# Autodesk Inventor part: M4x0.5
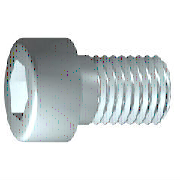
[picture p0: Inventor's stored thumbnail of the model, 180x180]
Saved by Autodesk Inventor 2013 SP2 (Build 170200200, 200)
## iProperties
IsCustomPart: 1
Company: 한국ATC센터
Created: 2014-11
Part Number: M4x0.5
Material: 강, 연강
Description: 6각머리 태핑 나사
Document SubType Name: Modeling
Standard: KS B 1003
Designer: KYOUNG IL JANG
Standards Organization: KS
Language: ko-KR
Size Designation: M 4 x 16
Categories: <MemberInstance><Categories><Category DisplayName="조임쇠" InternalName="e4da775c-781d-43d5-af7c-5136215cf5a6" Mnemonic="FSTN"><Category DisplayName="볼트" InternalN
Density: 7.86 g/cm^3
Mass: 2.62973 g
Surface Area: 3.81119 cm^2
Volume: 0.334572 cm^3
Author: KYOUNG IL JANG
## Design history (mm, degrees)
sketch "스케치1"
  geometry: L1 (-1, 0)-(16, 0); L2 (16, 0)-(16, 2); L3 (16, 2)-(1.75, 2); L4 (1.75, 2)-(1.32, 2); L5 (1.32, 2)-(0, 2); L6 (0, 2)-(0, 3.5); L7 (0, 3.5)-(-4, 3.5); L8 (-4, 3.5)-(-4, 1.732); L9 (-4, 1.732)-(-2, 1.732); L10 (-2, 1.732)-(-1, 0); L11 (-8, 0)-(20, 0) reference; L12 (0, -0.7)-(0, 4.2) reference; L13 (1.75, 2)-(0, 2)
  constraints: 22 end point, 6 parallel, 2 collinear, 2 perpendicular, 1 horizontal, 1 point on line
  dimensions: "d1" = 14.25 distance from line of L3.end L2 (= GEL); "d2" = 0.42952 distance of L4.end L3.end (computed from GAL); "d3" = 4 distance between parallel lines of L8 L6 (= KOH); "d4" = 2 distance of L8.end L9.end (= INTI); "d5" = 60 deg angle of L10 L1; "d6" = 4 diameter of L3 L1 (= GD); "d7" = 4 diameter of L5 L1 (= BDM); "d8" = 3.4641 diameter of L9 L1 (= 1.1547 x SW); "d9" = 7 diameter of L7 L1 (= KOD); "d26" = 16 distance between parallel lines of L12 L2 (= NLG)
revolve "본체" sketch "스케치1" stored, may be unused: angle "d10" = 90 deg
sketch "스케치2"
  geometry: L1 (0, -4.9)-(0, 4.9) reference; L2 (-4.9, 0)-(4.9, 0) reference; L3 (1.732, 0)-(0.866, -1.5); L4 (0.866, -1.5)-(-0.866, -1.5); L5 (-0.866, -1.5)-(-1.732, 0); L6 (-1.732, 0)-(-0.866, 1.5); L7 (-0.866, 1.5)-(0.866, 1.5); L8 (0.866, 1.5)-(1.732, 0); 2 further points
  constraints: 12 end point, 1 coincident, 1 horizontal alignment, 1 point on line, 12 other
extrude "슬롯" join sketch "스케치2" stored distance "d11" = 10; taper "d12" = 0 deg
workplane "Work Plane1"
fillet "Fillet2" dims "d30" = 0.1 (= R)
body "Solid1"
fillet "모깎기1" dims "d17" = 0.4 (= RR)
feature "스레드" dims "d13" = 14.25 (= GEL), "d14" = 0
chamfer "모따기1" distance "d15" = 0.42941 (= -0.5 x SPD + 0.5 x GD); stored, may be unused: second distance "d16" = 0.42941 (= GUL), angle "d27" = 45 deg
other parameters: "GD" = 4 (= NND) [user parameter; used in 2 equation terms], "NLG" = 16 [user parameter; used in 1 equation term], "GEL" = 14.25 [user parameter; used in 2 equation terms], "KOD" = 7 [user parameter; used in 1 equation term], "KOH" = 4 [user parameter; used in 1 equation term], "INTI" = 2 [user parameter; used in 1 equation term], "GAL" = 0.42941 (= 0.61345 x PTC) [user parameter; used in 1 equation term], "GUL" = 0.42941 (= 0.61345 x PTC) [user parameter; used in 1 equation term], "BDM" = 4 (= NND) [user parameter; used in 1 equation term], "SW" = 3 [user parameter; used in 2 equation terms], "RR" = 0.4 [user parameter; used in 1 equation term], "SPD" = 3.14117 (= NND - 1.2269 x PTC) [user parameter; used in 1 equation term], "d19" = 0, "d28" = 0, "d29" = 0, "R" = 0.1 [user parameter; used in 1 equation term], "PHH" = 0.2 [user parameter], "GD1" = 3.14117 (= THREADDIA - 1.2269 x PTC) [user parameter], "THREADDIA" = 4 [user parameter; used in 1 equation term], "FAWI" = 45 deg [user parameter], "TPU" = 14.28571 (computed from PTC) [user parameter], "PTC" = 0.7 [user parameter; used in 5 equation terms], "NND" = 4 [user parameter; used in 3 equation terms], "TOA" = 30 deg [user parameter], "E0" = 3.465 (= 1.155 x SW) [user parameter]
